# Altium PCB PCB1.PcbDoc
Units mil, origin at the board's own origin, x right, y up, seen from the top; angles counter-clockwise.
Board outline 4860 x 1890 mil, 2 copper layers (Top Layer, Bottom Layer); 13 components, 31 nets, 108 pads, 30 vias.
Unrouted connection lines stored in the file: 1.
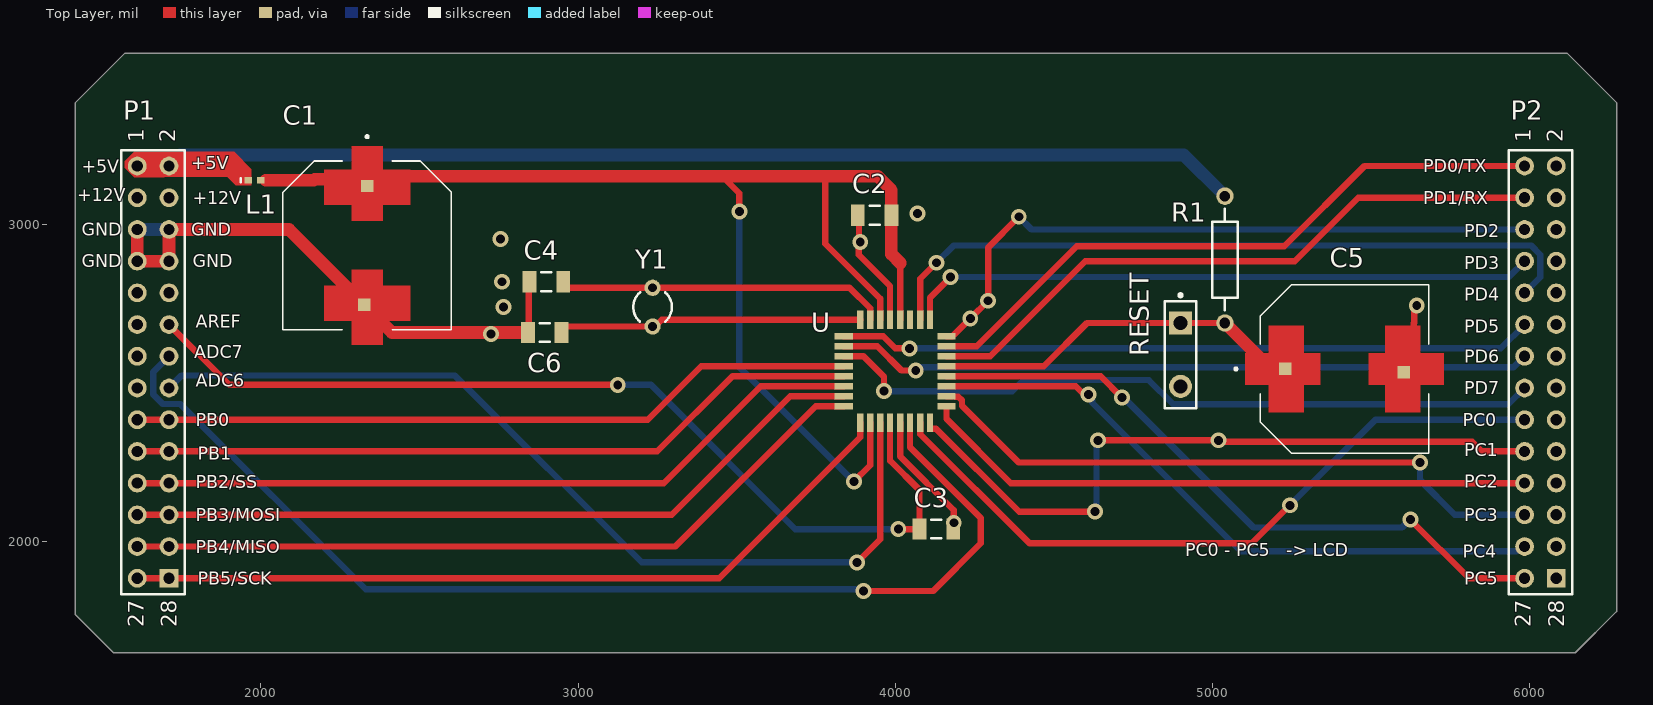
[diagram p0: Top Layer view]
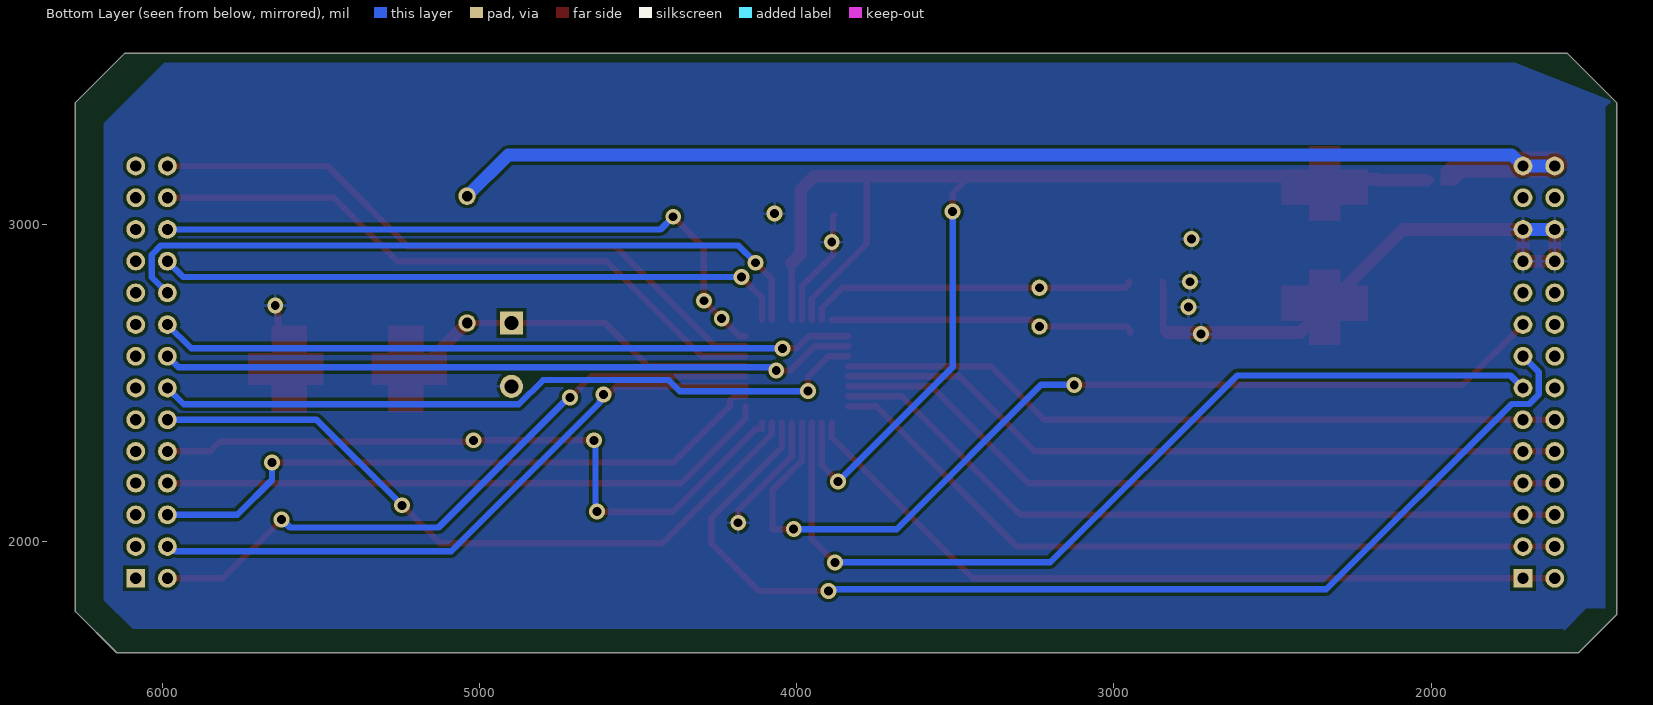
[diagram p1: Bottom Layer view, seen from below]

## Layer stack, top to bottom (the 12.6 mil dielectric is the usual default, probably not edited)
Top Solder: solder mask 0.4, Solder Resist, Dk 3.5
Top Layer: signal copper 1.4
Dielectric 1: dielectric 12.6, FR-4, Dk 4.8
Bottom Layer: signal copper 1.4
Bottom Solder: solder mask 0.4, Solder Resist, Dk 3.5

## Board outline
1535,1650 1415,1770 1415,3385 1570,3540 6120,3540 6275,3385 6275,1780 6145,1650

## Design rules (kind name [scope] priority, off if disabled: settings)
Clearance [All] p1: gap=10 ignorepadtopadclearanceinfootprint=FALSE except(0: Arc-Hole Track-Hole SMDPad-Hole THPad-Hole Via-Hole Fill-Hole Poly-Hole Region-Hole Text-Hole)
PolygonConnect [All] p1: connectstyle=Relief reliefconductorwidth=10 reliefentries=4 polygonreliefangle="90 Angle" airgapwidth=10
RoutingVias [All] p1: holewidth=28 width=50 viastyle="Through Hole" minholewidth=28 minwidth=50 maxholewidth=28 maxwidth=50
SolderMaskExpansion [All] p1: expansion=4 istentingtop=FALSE
Width [All] p1: maxlimit=120 minlimit=10 preferedwidth=40 minimp=50.000000 maximp=50.000000 favimp=50.000000
30 further rules are at their usual default settings.

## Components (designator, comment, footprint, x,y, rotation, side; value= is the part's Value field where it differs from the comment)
C1 "Cap Pol1" CAP_EEV-FK0J332V 2335,2935 r270 top value=10U
C2 "Cap Semi" C1206 3935,3030 r0 top value=22pF
C3 "Cap Semi" C1206 4130,2040 r180 top value=0.1UF
C4 "Cap Semi" C1206 2900,2820 r0 top value=22pF
C5 "Cap Pol1" CAP_EEV-FK0J332V 5417.01,2545 r0 top value=10U
C6 "Cap Semi" C1206 2895,2660 r0 top value=22pF
L1 "Ferrite Bead" 0402-A 1980,3140 r0 top value=10mH
P1 "Header 14X2H" HEADER 365,1665 r0 top
P2 "Header 14X2H" HEADER 4740,1665 r0 top
R1 "Res2" AXIAL-0.4 5040,2890 r90 top value=10K
RESET "SW-PB" SPST-2 4900,2590 r270 top
U "ATMEGA8-16AU" QFP80P900X900X120-32N 4000,2537.91 r270 top
Y1 "16M" R38 3235,2740 r180 top

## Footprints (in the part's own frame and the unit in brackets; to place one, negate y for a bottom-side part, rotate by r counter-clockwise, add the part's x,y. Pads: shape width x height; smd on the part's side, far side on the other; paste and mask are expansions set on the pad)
0402-A [mm] "Chip Inductor, Body 1.0x0.5mm, IPC High Density"
  rect 0.6x0.5 smd: 1(-0.5,0) 2(0.5,0)
  silkscreen extent -1.1,-0.15 -1.1,0.15, body extent -0.55,-0.3 0.55,0.3, height 0.55
AXIAL-0.4 [mm] "Axial Device, Thru-Hole; 2 Leads; 0.4 in Pin Spacing"
  round 1.4 hole 0.85: 1(-5.08,0) 2(5.08,0)
  silkscreen extent -4.06,-1.02 4.06,1.02
C1206 [mm] "Chip Capacitor, Body 3.2x1.6mm, IPC High Density"
  rect 1.1x1.7 smd: 1(-1.35,0) 2(1.35,0)
  silkscreen extent -0.4,-0.75 0.4,0.75, body extent -1.7,-0.9 1.7,0.9, height 1.3
CAP_EEV-FK0J332V [mm]
  rect 1x1 smd paste-1 mask+0: 1(-4.75,0) 2(4.75,-0.25)
  Top Layer region: -3.25,1.25 -1.95,1.25 -1.95,-1.25 -3.25,-1.25 -3.25,-3.45 -6.05,-3.45 -6.05,-1.25 -7.95,-1.25 -7.95,1.25 -6.05,1.25 -6.05,3.45 -3.25,3.45
  Top Layer region: 6.05,1.25 7.95,1.25 7.95,-1.25 6.05,-1.25 6.05,-3.45 3.25,-3.45 3.25,-1.25 1.95,-1.25 1.95,1.25 3.25,1.25 3.25,3.45 6.05,3.45
  silkscreen extent -8.8,-6.75 6.75,6.75
HEADER [mm]
  round 1.5 hole 0.9: 1(31.623,38.608) 2(34.163,38.608) 3(31.623,36.068) 4(34.163,36.068) 5(31.623,33.528) 6(34.163,33.528) 7(31.623,30.988) 8(34.163,30.988) 9(31.623,28.448) 10(34.163,28.448) 11(31.623,25.908) 12(34.163,25.908) 13(31.623,23.368) 14(34.163,23.368) 15(31.623,20.828) 16(34.163,20.828) 17(31.623,18.288) 18(34.163,18.288) 19(31.623,15.748) 20(34.163,15.748) 21(31.623,13.208) 22(34.163,13.208) 23(31.623,10.668) 24(34.163,10.668) 25(31.623,8.128) 26(34.163,8.128) 27(31.623,5.588)
  rect 1.5x1.5 hole 0.9: 28(34.163,5.588)
  silkscreen extent 30.35,4.32 35.43,39.88
QFP80P900X900X120-32N [mil]
  rect 58x20 smd: 1(-162,110) 2(-162,79) 3(-162,47) 4(-162,16) 5(-162,-16) 6(-162,-47) 7(-162,-79) 8(-162,-110) 17(162,-110) 18(162,-79) 19(162,-47) 20(162,-16) 21(162,16) 22(162,47) 23(162,79) 24(162,110)
  rect 20x58 smd: 9(-110,-162) 10(-79,-162) 11(-47,-162) 12(-16,-162) 13(16,-162) 14(47,-162) 15(79,-162) 16(110,-162) 25(110,162) 26(79,162) 27(47,162) 28(16,162) 29(-16,162) 30(-47,162) 31(-79,162) 32(-110,162)
R38 [mm] "Crystal, Thru-Hole; 2 Leads; Body 3.1 x 8.2 mm (Dia.xH)"
  round 1.3 hole 0.7: 1(0,1.55) 2(0,-1.55)
  silkscreen extent -1.55,-1.19 1.55,1.17
SPST-2 [mm] "Switch; 2 Leads"
  rect 1.85x1.85 hole 1.1: 1(-2.54,0)
  round 1.85 hole 1.1: 2(2.54,0)
  silkscreen extent -4.89,-1.27 4.28,1.27

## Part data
C1 C5: "Polarized Capacitor (Radial)"
C2 C3 C4 C6: "Capacitor (Semiconductor SIM Model)"
L1: library part Inductor, "Inductor"
P1 P2: "Header, 14-Pin, Dual row, Right Angle"
R1: "Resistor"
RESET: "Switch"
U: "AVR AVRÂ® ATmega Microcontroller IC 8-Bit 16MHz 8KB _4K x 16_ FLASH 32-TQFP _7x7_", Package="TQFP-32 Microchip Technology"
Y1: library part XTAL, "Crystal Oscillator"

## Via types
v1: diameter 50, hole 28, Top Layer to Bottom Layer, 30 vias

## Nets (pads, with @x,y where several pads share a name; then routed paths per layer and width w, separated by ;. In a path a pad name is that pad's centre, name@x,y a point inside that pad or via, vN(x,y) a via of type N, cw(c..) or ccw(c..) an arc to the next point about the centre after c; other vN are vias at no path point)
+3.3V: P1.3
+12V: P1.4
ADC6: P1.16 U.19 | length 2901.7
  Top Layer w20: v1(3880,1935) 3953,2008 U.19
  Bottom Layer w20: P1.16 1749.53,2524.53 2611.72,2524.53 3201.24,1935 v1(3880,1935)
ADC7: P1.14 U.22 | length 3542.6
  Top Layer w20: v1(3900,1845) 4120,1845 4270,1995 4270,2075 4047,2298 U.22
  Bottom Layer w20: P1.14 1660.47,2535.47 1660.47,2464.49 1690.43,2434.53 1745.47,2434.53 2330,1850 3895,1850 v1(3900,1845)
GND: C1.2 C2.1 C3.1 C4.1 C5.2 C6.1 P1.5 P1.6 P1.7 P1.8 RESET.2 U.3 U.5 U.21 | length 2807.8
  Top Layer w20: C6.1 2844.35,2662.5 2844.35,2817.5 C4.1 ; C2.1 3885.93,3025.93 3885.93,2949.07 v1(3890,2945) 3885,2940 3885,2905 3984,2806 U.5 ; U.21 4016,2269 4185,2100 v1(4185,2060) ; C5.2 5604.02,2629.65 5635.2,2660.83 5635.2,2689.11 5636.8,2690.71 5636.8,2736.8 v1(5645,2745)
  Top Layer w40: P1.5 P1.7 P1.8 P1.6 2088.15,2985 C1.2 2413.15,2660 C6.1@2831.85,2660
  Bottom Layer w40: P1.5 P1.6
  other v1: 2725,2655 2765,2740 2760,2820 2755,2955 4070,3035
NetC1_1: C1.1 C2.2 L1.2 U.4 U.6 U.18 | length 4317.9
  Top Layer w20: L1.2 2015,3140 ; 3455,3153 3508.68,3099.32 v1(3508.68,3041.32) ; 3765,3153 3780,3138 3780,2940 3953,2767 U.6 ; v1(3870,2190) 3921,2241 U.18 ; U.4 4016,2879.34
  Top Layer w40: 2015,3140 2165.98,3140 2169.17,3143.19 2356.18,3143.19 2365.99,3153 3455,3153 3765,3153 3780,3153 3944.15,3153 3988.15,3109 C2.2 3988.15,2907.19 4016,2879.34
  Bottom Layer w20: v1@3500,3050 v1(3508.68,3041.32) 3508.68,2551.32 v1(3870,2190)
NetC3_2: C3.2 P1.12 U.20 | length 3008.4
  Top Layer w20: P1.12 1900,2495 v1(3125,2495) ; U.20 3984,2256 4076.85,2163.15 C3.2 v1(4010,2040)
  Bottom Layer w20: v1(3125,2495) 3230,2495 3685,2040 v1(4010,2040)
NetC4_2: C4.2 U.7 Y1.2 | length 1043.1
  Top Layer w20: C4.2 2953.15,2812.68 2964.8,2801.02 Y1.2 3856.17,2801.02 3921,2736.19 U.7
NetC5_1: C5.1 R1.1 RESET.1 U.29 | length 1184.4
  Top Layer w20: U.29 4468.91,2553.91 4605,2690 RESET.1 R1.1
  Top Layer w40: R1.1 5185,2545 C5.1
NetC6_2: C6.2 U.8 Y1.1 | length 962.7
  Top Layer w20: C6.2 2948.15,2667.32 2959.8,2678.98 Y1.1 3243.44,2678.98 3264.37,2699.91 U.8
PB0: P1.17 P1.18 U.12 | length 2298
  Top Layer w20: P1.17 P1.18 3220,2385 3388.91,2553.91 U.12
PB1: P1.19 P1.20 U.13 | length 2326.1
  Top Layer w20: P1.19 P1.20 3250,2285 3486.91,2521.91 U.13
PB2: P1.21 P1.22 U.14 | length 2354.7
  Top Layer w20: P1.21 P1.22 3270,2185 3575.91,2490.91 U.14
PB3: P1.23 P1.24 U.15 | length 2382.9
  Top Layer w20: P1.23 P1.24 3295,2085 3668.91,2458.91 U.15
PB4: P1.25 P1.26 U.16 | length 2411.5
  Top Layer w20: P1.25 P1.26 3306.72,1985 3749.62,2427.91 U.16
PB5: P1.27 P1.28 U.17 | length 2510.2
  Top Layer w20: P1.27@1605,1885 P1.28@1705,1885 ; P1.28 3445,1885 3890,2330 U.17
PC0: P2.17 U.23 | length 2246.6
  Top Layer w20: U.23 4079,2339.62 4423.62,1995 5125,1995 v1(5245,2115)
  Bottom Layer w20: v1(5245,2115) 5515,2385 P2.17
PC1: P2.19 U.24 | length 2245.6
  Top Layer w20: U.24 4110,2356.91 4129,2356.91 4390.91,2095 v1(4630,2095) ; v1(4640,2320) 5006.14,2320 5010,2323.86 5010,2328.28 5023.43,2328.28 5036.72,2315 5820,2315 5850,2285 P2.19
  Bottom Layer w20: v1(4630,2095) 4635,2100 4635,2315 v1(4640,2320)
  other v1: 5020,2320
PC2: P2.21 U.25 | length 1947
  Top Layer w20: U.25 4162,2388 4365,2185 P2.21
PC3: P2.23 U.26 | length 2020.2
  Top Layer w20: U.26 4186.86,2458.91 4187.86,2457.91 4199.28,2457.91 4211,2446.19 4211,2429 4390,2250 v1(5655,2250)
  Bottom Layer w20: v1(5655,2250) 5655,2195 5765,2085 P2.23
PC4: P2.25 U.27 | length 2053.8
  Top Layer w20: U.27 4569.09,2490.91 4595,2465 v1(4610,2465)
  Bottom Layer w20: v1(4610,2465) 4610,2456.88 4621.39,2445.49 4621.39,2438.61 5090,1970 5959.43,1970 5974.43,1985 P2.25
PC5: P2.27 U.28 | length 2107.5
  Top Layer w20: U.28 4648.09,2521.91 v1(4715,2455) ; v1(5625,2070) 5810,1885 P2.27
  Bottom Layer w20: v1(4715,2455) 4720,2455 5130,2045 5598.28,2045 5623.28,2070 v1(5625,2070)
PD0: P2.3 U.30 | length 2036.7
  Top Layer w20: U.30 4299.91,2584.91 4600,2885 5260,2885 5460,3085 P2.3@5991.52,3085
PD1: P2.1 U.31 | length 2058.3
  Top Layer w20: U.31 4256.91,2616.91 4572.5,2932.5 5227.5,2932.5 5480,3185 P2.1
PD2: P2.5 U.32 | length 2094.2
  Top Layer w20: U.32 4181,2647.91 v1(4237.05,2703.95) v1(4293.09,2760) 4293.09,2928.09 v1(4390,3025)
  Bottom Layer w20: v1(4390,3025) 4430,2985 P2.5
PD3: P2.7 U.1 | length 1992.7
  Top Layer w20: U.1 4110,2770 v1(4175,2835)
  Bottom Layer w20: v1(4175,2835) 5935,2835 P2.7
PD4: P2.9 U.2 | length 2281.4
  Top Layer w20: U.2 4079,2829 v1(4130,2880)
  Bottom Layer w20: v1(4130,2880) 4184.53,2934.53 6005.52,2934.53 6034.53,2905.51 6034.53,2834.53 P2.9
PD5: P2.11 U.9 | length 2193.8
  Top Layer w20: U.9 3962.09,2647.91 4000,2610 v1(4045,2610)
  Bottom Layer w20: v1(4045,2610) 5910,2610 P2.11
PD6: P2.13 U.10 | length 2197.5
  Top Layer w20: U.10 3943.09,2616.91 4020,2540 v1(4065,2540)
  Bottom Layer w20: v1(4065,2540) 4075,2550 5950,2550 P2.13
PD7: P2.15 U.11 | length 2286.3
  Top Layer w20: U.11 3900.09,2584.91 3965,2520 v1(3965,2475)
  Bottom Layer w20: v1(3965,2475) 4369.17,2475 4404.17,2510 4800.21,2510 4876.63,2433.58 5933.58,2433.58 P2.15
VCC: L1.1 P1.1 P1.2 R1.2 | length 3498.3
  Bottom Layer w40: P1.1 P1.2 1745,3220 4910,3220 R1.2
pads on no net: P1.9 P1.10 P1.11 P1.13 P1.15 P2.2 P2.4 P2.6 P2.8 P2.10 P2.12 P2.14 P2.16 P2.18 P2.20 P2.22 P2.24 P2.26 P2.28

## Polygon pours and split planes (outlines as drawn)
GND on Bottom Layer "GND_L02_P000" (solid, pour order 0): 1430,3390 1450,3370 1450,1790 1510,1790 1580,1720 1585,1725 6095,1725 6185,1815 6185,3320 5995,3510 1735,3510

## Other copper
Top Layer:
  region net VCC: 1695,3150 1895,3150 1920,3125 1970,3125 1970,3175 1915,3230 1600,3230 1570,3200 1570,3180 1600,3150 1670,3150

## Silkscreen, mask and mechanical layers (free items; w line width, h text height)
Top Overlay:
  text "+5V" at 1780.04,3174.37 h40
  text "PD0/TX" at 5665,3165 h40
  text "+5V" at 1435.04,3164.37 h40
  text "+12V" at 1420.04,3074.37 h40
  text "PD1/RX" at 5665,3065 h40
  text "+12V" at 1785.04,3064.37 h40
  text "GND" at 1435,2965 h40
  text "GND" at 1780.04,2964.37 h40
  text "PD2" at 5795,2960 h40
  text "GND" at 1435,2865 h40
  text "GND" at 1785,2865 h40
  text "PD3" at 5795,2860 h40
  text "PD4" at 5795,2760 h40
  text "AREF" at 1795.04,2674.37 h40
  text "PD5" at 5795,2660 h40
  text "ADC7" at 1790.04,2579.37 h40
  text "PD6" at 5795,2565 h40
  text "ADC6" at 1795.04,2489.37 h40
  text "PD7" at 5795,2465 h40
  text "PC0" at 5790,2365 h40
  text "PB0" at 1795.04,2364.37 h40
  text "PC1" at 5795,2270 h40
  text "PB1" at 1800.04,2259.37 h40
  text "PC2" at 5795,2170 h40
  text "PB2/SS" at 1795.04,2169.37 h40
  text "PC3" at 5795,2065 h40
  text "PB3/MOSI" at 1795.04,2064.37 h40
  text "PB4/MISO" at 1795.04,1964.37 h40
  text "PC0 - PC5   -> LCD" at 4915,1955 h40
  text "PC4" at 5790,1950 h40
  text "PC5" at 5795,1865 h40
  text "PB5/SCK" at 1800.04,1864.37 h40
Mechanical 1:
  lines w10: 1415,1770 1535,1650 4410,1650 6145,1650 6275,1780 6275,3385 6120,3540 1570,3540 1415,3385 1415,1770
